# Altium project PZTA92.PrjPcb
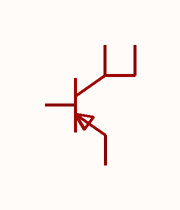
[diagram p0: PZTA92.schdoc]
1 sheet, 1 parts. Net scope: global (net labels, ports and power ports of the same name join across sheets).

## Sheet PZTA92.schdoc
size 127 x 101 mm

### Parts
Q?  pzta92  [SOT-223-3_L6.5-W3.4-P2.30-LS7.0-BR]  (value not drawn)

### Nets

Not connected (* = marked no-connect by the designer): Q? 1(B) 2(C) 3(E) 4(C)

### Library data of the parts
Q? = pzta92: 晶体管类型:PNP;集电极电流(Ic):200mA;集射极击穿电压(Vceo):300V;耗散功率(Pd):1W;直流电流增益(hFE):25;; Manufacturer: CJ(江苏长电/长晶); AddInBom: yes; ModelId: 925194bf9823436183a3e0b978a8d076; ModelName: SOT-223-4P_L6.5-W3.5-H1.6-LS7.0-P2.30; ModelTransform: 279.89794,255.905,0,180,0,0,-3.9385,-0.0005,0; type: PNP; Current - Collector(Ic): 200mA; Collector - Emitter Voltage VCEO: 300V; Pd - Power Dissipation: 1W; DC Current Gain: 25; Transition frequency(fT): 50MHz; Current - Collector Cutoff: 250nA; Vce Saturation(VCE(sat)): 500mV; Emitter-Base Voltage(Vebo): 5V; Number: 1个PNP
